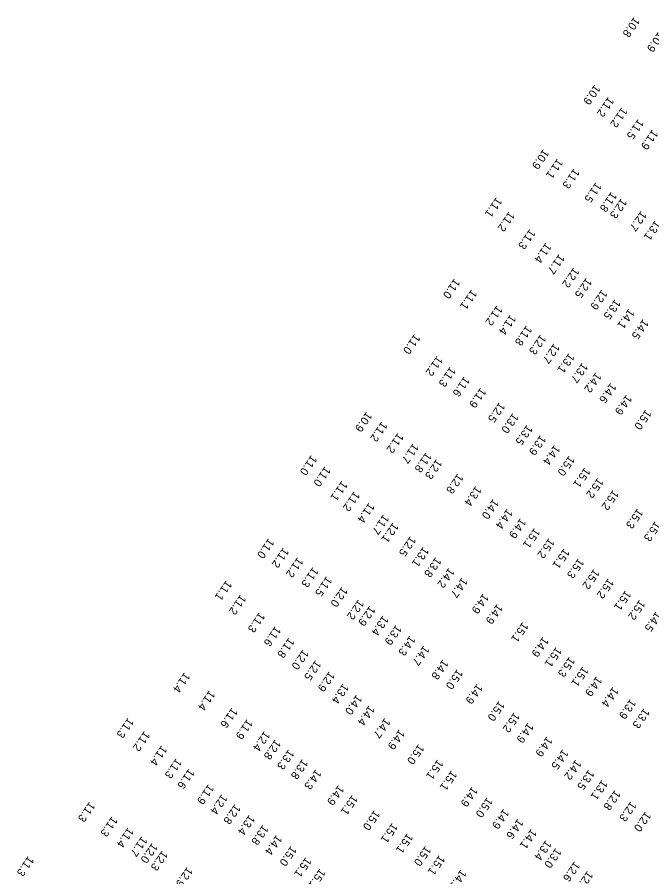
# Model space of a CAD drawing. Extents: x 815385 to 820851, y 582449 to 604245.
# Drawn here: x 816022 to 816418, y 583540 to 584076 of the extents above; entities that cross this region are included whole.
import ezdxf

# ---------------------------------------------------------------- set-up
doc = ezdxf.new("R2010")
doc.units = 0
doc.layers.add('V-TOPO-SOUN-101408', color=7, linetype='Continuous')

msp = doc.modelspace()

# ---------------------------------------------------------------- texts
at = {"layer": 'V-TOPO-SOUN-101408'}
for s, p in [('10.8 ', (816407.19, 584076.64)), ('10.9 ', (816422.25, 584067.32)), ('10.9 ', (816382.55, 584034.4)), ('11.2 ', (816391.09, 584026.8)), ('11.2 ', (816399.46, 584020.26)), ('11.5 ', (816409.66, 584012.91)), ('11.9 ', (816418.54, 584006.35)), ('10.9 ', (816350.54, 583994.16)), ('11.1 ', (816359.27, 583988.28)), ('11.3 ', (816369.6, 583982.05)), ('11.5 ', (816383.29, 583973.41)), ('11.1 ', (816321.2, 583964.13)), ('11.8 ', (816392.88, 583967.47)), ('12.3 ', (816399.15, 583963.39)), ('11.2 ', (816329.14, 583955.21)), ('12.7 ', (816411.45, 583955.49)), ('13.1 ', (816420.31, 583949.67)), ('11.3 ', (816341.99, 583944.23)), ('11.4 ', (816352.06, 583935.65)), ('11.7 ', (816360.27, 583928.61)), ('12.2 ', (816369.42, 583920.25)), ('11.0 ', (816295.02, 583913.37)), ('12.5 ', (816377.26, 583913.73)), ('11.1 ', (816305.66, 583906.48)), ('12.9 ', (816386.93, 583906.4)), ('13.5 ', (816395.19, 583900.43)), ('11.2 ', (816321.5, 583896.53)), ('14.1 ', (816403.86, 583894.52)), ('11.4 ', (816329.92, 583890.83)), ('11.8 ', (816339.89, 583884.02)), ('14.5 ', (816412.75, 583888.03)), ('11.0 ', (816270.15, 583878.74)), ('12.3 ', (816348.72, 583878.44)), ('12.7 ', (816357.14, 583872.87)), ('11.2 ', (816284.19, 583865.04)), ('13.1 ', (816366.41, 583866.75)), ('11.3 ', (816292.35, 583858.26)), ('13.7 ', (816374.77, 583860.76)), ('11.6 ', (816301.11, 583852.2)), ('14.2 ', (816383.17, 583854.73)), ('14.6 ', (816392.5, 583848.17)), ('11.9 ', (816311.31, 583845.17)), ('14.9 ', (816402.27, 583840.79)), ('12.5 ', (816323.05, 583836.1)), ('10.9 ', (816240.1, 583830.16)), ('13.0 ', (816331.43, 583829.34)), ('15.0 ', (816414.38, 583831.54)), ('11.2 ', (816249.61, 583824.04)), ('13.5 ', (816340.25, 583821.97)), ('11.2 ', (816259.76, 583816.96)), ('13.9 ', (816348.61, 583815.58)), ('11.7 ', (816269.25, 583810.46)), ('14.4 ', (816357.43, 583809.51)), ('11.0 ', (816205.7, 583803.08)), ('11.8 ', (816277.31, 583804.87)), ('15.0 ', (816366.52, 583802.7)), ('12.3 ', (816283.8, 583800.68)), ('11.0 ', (816214.19, 583796.04)), ('15.1 ', (816376.28, 583795.32)), ('11.1 ', (816224.78, 583787.01)), ('12.8 ', (816297.02, 583791.57)), ('15.2 ', (816384.44, 583788.91)), ('13.4 ', (816308.35, 583783.83)), ('15.2 ', (816393.98, 583781.35)), ('11.2 ', (816232.48, 583780.54)), ('14.0 ', (816319.21, 583775.73)), ('11.4 ', (816241.66, 583773.37)), ('11.7 ', (816250.74, 583766.07)), ('14.4 ', (816327.83, 583769.59)), ('15.3 ', (816409.21, 583769.8)), ('12.1 ', (816256.62, 583761.01)), ('14.9 ', (816336.19, 583763.7)), ('15.3 ', (816420.34, 583761.8)), ('15.1 ', (816344.91, 583757.57)), ('11.0 ', (816179.01, 583751.15)), ('12.5 ', (816267.48, 583752.49)), ('15.2 ', (816353.95, 583751.24)), ('11.2 ', (816188.18, 583745.32)), ('13.1 ', (816275.55, 583745.83)), ('15.1 ', (816363.36, 583744.81)), ('11.2 ', (816197.1, 583739.3)), ('13.8 ', (816283.3, 583739.38)), ('15.3 ', (816372.38, 583738.71)), ('11.3 ', (816206.65, 583733.13)), ('14.2 ', (816291.5, 583732.77)), ('11.5 ', (816215.19, 583727.46)), ('15.2 ', (816382.03, 583732.01)), ('11.1 ', (816152.61, 583724.89)), ('14.7 ', (816299.73, 583726.64)), ('15.2 ', (816390.99, 583726.14)), ('12.0 ', (816224.81, 583720.84)), ('14.9 ', (816312.94, 583716.69)), ('15.1 ', (816401.76, 583718.67)), ('11.2 ', (816161.45, 583716)), ('12.2 ', (816235.06, 583712.93)), ('15.2 ', (816410.53, 583712.74)), ('12.9 ', (816242.08, 583708.99)), ('14.9 ', (816321.69, 583710.19)), ('11.3 ', (816173.23, 583704.96)), ('13.4 ', (816250.37, 583702.96)), ('14.5 ', (816420.84, 583705.48)), ('11.6 ', (816183.17, 583696.31)), ('13.9 ', (816258.56, 583697.1)), ('15.1 ', (816337.56, 583698.81)), ('14.3 ', (816267.17, 583690.4)), ('11.8 ', (816191.64, 583689.08)), ('14.9 ', (816350.25, 583689.62)), ('12.0 ', (816200.5, 583681.74)), ('14.7 ', (816275.84, 583684.22)), ('15.1 ', (816358.49, 583683.29)), ('12.5 ', (816208.32, 583675.06)), ('14.8 ', (816287.77, 583675.53)), ('15.3 ', (816366.73, 583677.15)), ('15.0 ', (816296.77, 583669.46)), ('15.1 ', (816375.09, 583671.14)), ('11.4 ', (816126.54, 583667.46)), ('12.9 ', (816216.84, 583668.03)), ('14.9 ', (816383.64, 583665.05)), ('13.4 ', (816225.52, 583660.48)), ('14.9 ', (816309.1, 583660.3)), ('14.4 ', (816393.9, 583658.37)), ('11.4 ', (816142.07, 583656.25)), ('14.0 ', (816233.89, 583653.53)), ('14.4 ', (816241.7, 583646.87)), ('15.0 ', (816322.85, 583649.64)), ('13.9 ', (816404.81, 583650.87)), ('11.6 ', (816156.13, 583645.39)), ('15.2 ', (816332.28, 583642.52)), ('13.3 ', (816413.3, 583645.06)), ('11.3 ', (816091.36, 583639.09)), ('11.9 ', (816165.63, 583638.23)), ('14.7 ', (816251.47, 583638.92)), ('11.2 ', (816101.48, 583630.78)), ('12.4 ', (816176.43, 583630.81)), ('14.9 ', (816260.53, 583631.82)), ('14.9 ', (816340.88, 583635.97)), ('12.8 ', (816183.16, 583625.57)), ('14.9 ', (816352.67, 583627.4)), ('11.4 ', (816112.18, 583621.81)), ('15.0 ', (816272.62, 583622.64)), ('13.3 ', (816191.48, 583619.35)), ('14.5 ', (816362.61, 583619.5)), ('11.3 ', (816121.36, 583613.77)), ('13.8 ', (816200.07, 583613.3)), ('15.1 ', (816284.49, 583613.1)), ('14.2 ', (816370.67, 583612.95)), ('11.6 ', (816129.28, 583607.31)), ('14.3 ', (816208.44, 583606.91)), ('15.1 ', (816293.1, 583606.22)), ('13.5 ', (816378.75, 583606.68)), ('13.1 ', (816387.11, 583600.35)), ('11.9 ', (816141.47, 583597.62)), ('14.9 ', (816222.61, 583597.07)), ('14.9 ', (816306.04, 583596.11)), ('12.8 ', (816395.15, 583593.99)), ('12.4 ', (816149.82, 583591.36)), ('15.1 ', (816231.19, 583590.93)), ('15.0 ', (816315.41, 583589.43)), ('11.3 ', (816067.25, 583586.64)), ('12.8 ', (816158, 583585.17)), ('12.3 ', (816405.06, 583586.95)), ('11.3 ', (816081.25, 583577.5)), ('13.4 ', (816166.95, 583578.51)), ('15.0 ', (816245.02, 583581.42)), ('14.9 ', (816325.63, 583582.25)), ('12.0 ', (816414.19, 583580.59)), ('13.8 ', (816175.42, 583572.24)), ('15.1 ', (816256.14, 583573.44)), ('14.6 ', (816334.55, 583576.09)), ('11.4 ', (816091.34, 583570.64)), ('15.1 ', (816265.64, 583567)), ('14.1 ', (816342.91, 583569.75)), ('11.7 ', (816099.83, 583565.05)), ('12.0 ', (816106.29, 583560.9)), ('14.4 ', (816183.92, 583566.02)), ('13.4 ', (816352.04, 583562.67)), ('12.3 ', (816112.62, 583556.2)), ('15.0 ', (816193.02, 583559.1)), ('15.0 ', (816276.92, 583559.12)), ('13.0 ', (816358.24, 583557.85)), ('11.3 ', (816029.04, 583552.78)), ('15.1 ', (816202.23, 583552.04)), ('15.1 ', (816285.54, 583553.39)), ('12.9 ', (816128.21, 583545.95)), ('15.1 ', (816211.01, 583544.92)), ('12.6 ', (816369.93, 583549.41)), ('14.9 ', (816299, 583544.4)), ('12.4 ', (816378.01, 583543.5))]:
    msp.add_text(s, height=5, rotation=234.911, dxfattribs=at).set_placement(p)

doc.saveas('drawing.dxf')
